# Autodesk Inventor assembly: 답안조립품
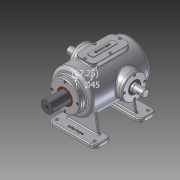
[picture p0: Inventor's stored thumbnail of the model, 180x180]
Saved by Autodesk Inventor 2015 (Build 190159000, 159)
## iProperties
Created: 2016-02
Part Number: 답안조립품
Document SubType Name: Assembly
Designer: Administrator
Author: Administrator
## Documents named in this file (15)
- C:\Users\Administrator\Desktop\360220V1005\답안조립품.iam
- C:\Users\Administrator\Desktop\360220V1005\본체.ipt
- C:\Users\Administrator\Desktop\360220V1005\슬라이드 커버.ipt
- C:\Users\Administrator\Desktop\360220V1005\부시.ipt
- C:\Users\Administrator\Desktop\360220V1005\볼트 M4x0.7.ipt
- C:\Users\Administrator\Desktop\360220V1005\상부커버.ipt
- C:\Users\Administrator\Desktop\360220V1005\육각머리볼트 M4.ipt
- C:\Users\Administrator\Desktop\360220V1005\베어링 6205.ipt
- 베어링 6205.ipt
- C:\Users\Administrator\Desktop\360220V1005\축 커버.ipt
- C:\Users\Administrator\Desktop\360220V1005\편심축.ipt
- C:\Users\Administrator\Desktop\360220V1005\오일실.ipt
- 오일실.ipt
- C:\Users\Administrator\Desktop\360220V1005\슬라이드.ipt
- C:\Users\Administrator\Desktop\360220V1005\가변스프링.ipt
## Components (13 placed, 2 different names)
1. 가변스프링:1
2. M4x0.7:1
3. M4x0.7:2
4. M4x0.7:3
5. M4x0.7:4
6. M4x0.7:5
7. M4x0.7:6
8. M4x0.7:7
9. M4x0.7:8
10. M4x0.7:9
11. M4x0.7:10
12. M4x0.7:11
13. M4x0.7:12
